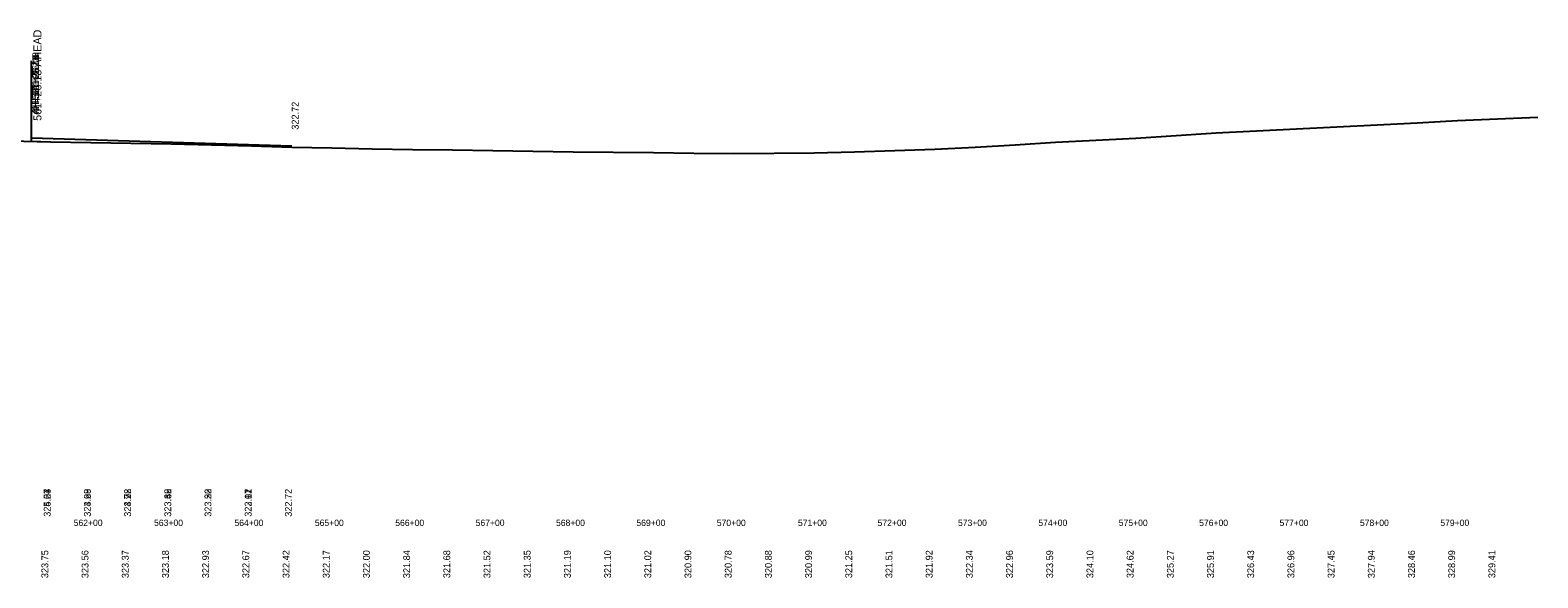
# Model space of a CAD drawing. Extents: x 1354 to 11940, y 17935 to 18885.
# Drawn here: x 10064 to 11940, y 17935 to 18616 of the extents above; entities that cross this region are included whole.
import ezdxf

# ---------------------------------------------------------------- set-up
doc = ezdxf.new("R2010")
doc.units = 0
for name, color, linetype in [('Level 1', 7, 'Continuous'), ('Level 40', 7, 'Continuous'), ('Level 41', 7, 'Continuous'), ('Level 42', 7, 'Continuous'), ('Level 43', 7, 'Continuous'), ('Level 45', 7, 'Continuous')]:
    doc.layers.add(name, color=color, linetype=linetype)

msp = doc.modelspace()

# ---------------------------------------------------------------- linework, layer by layer
at = {"layer": 'Level 1'}
msp.add_line((10065.9, 18477.7), (10065.9, 18577.7), dxfattribs=at)
at = {"layer": 'Level 40'}
for points in [[(10065.9, 18477.7), (10089.7, 18477.2), (10139.7, 18476.3), (10189.7, 18475.3), (10239.7, 18474.4), (10289.7, 18473.1), (10339.7, 18471.9), (10389.7, 18470.6), (10439.7, 18469.4), (10489.7, 18468.5), (10539.7, 18467.7), (10589.7, 18466.9), (10639.7, 18466.1), (10689.7, 18465.3), (10739.7, 18464.5), (10789.7, 18464), (10839.7, 18463.6), (10889.7, 18463), (10939.7, 18462.4), (10989.7, 18462.9), (11039.7, 18463.5), (11089.7, 18464.8), (11139.7, 18466.1), (11189.7, 18468.1), (11239.7, 18470.2), (11289.7, 18473.3), (11339.7, 18476.5), (11389.7, 18479), (11439.7, 18481.6), (11489.7, 18484.8), (11539.7, 18488.1), (11589.7, 18490.7), (11639.7, 18493.3), (11689.7, 18495.8), (11739.7, 18498.2), (11789.7, 18500.8), (11839.7, 18503.5), (11889.7, 18505.6), (11939.7, 18507.7)], [(10039.7, 18478.1), (10089.7, 18477.2), (10139.7, 18476.3), (10189.7, 18475.3), (10239.7, 18474.4), (10289.7, 18473.1), (10339.7, 18471.9), (10389.7, 18470.6)]]:
    msp.add_lwpolyline(points, dxfattribs=at)
at = {"layer": 'Level 45'}
msp.add_line((10065.9, 18481.9), (10389.7, 18472.1), dxfattribs=at)

# ---------------------------------------------------------------- texts
at = {"layer": 'Level 1'}
msp.add_text('561+26.18 AHEAD', height=10, rotation=90, dxfattribs=at).set_placement((10078.3, 18503.1))
at = {"layer": 'Level 41'}
for s, p in [('AH 561+26.18', (10075.4, 18515.4)), ('AH 561+26.18', (10075.4, 18512.5)), ('AH 561+26.18', (10075.4, 18510.9)), ('322.72', (10398.2, 18492.1))]:
    msp.add_text(s, height=8.5, rotation=90, dxfattribs=at).set_placement(p)
at = {"layer": 'Level 42'}
for s, p in [('562+00', (10118.4, 17999.5)), ('562+00', (10118.4, 17999.5)), ('563+00', (10218.4, 17999.5)), ('563+00', (10218.4, 17999.5)), ('564+00', (10318.4, 17999.5)), ('564+00', (10318.4, 17999.5)), ('565+00', (10418.4, 17999.5)), ('566+00', (10518.4, 17999.5)), ('567+00', (10618.4, 17999.5)), ('568+00', (10718.4, 17999.5)), ('569+00', (10818.4, 17999.5)), ('570+00', (10918.4, 17999.5)), ('571+00', (11019.3, 17999.5)), ('572+00', (11118.4, 17999.5)), ('573+00', (11218.4, 17999.5)), ('574+00', (11318.4, 17999.5)), ('575+00', (11418.4, 17999.5)), ('576+00', (11518.4, 17999.5)), ('577+00', (11618.4, 17999.5)), ('578+00', (11718.4, 17999.5)), ('579+00', (11818.4, 17999.5))]:
    msp.add_text(s, height=8, dxfattribs=at).set_placement(p)
at = {"layer": 'Level 43'}
for s, p in [('324.24', (10089.7, 18011)), ('324.53', (10089.7, 18011)), ('325.07', (10089.7, 18011)), ('324.68', (10139.7, 18011)), ('324.23', (10139.7, 18011)), ('323.99', (10139.7, 18011)), ('324.28', (10189.7, 18011)), ('323.73', (10189.7, 18011)), ('323.92', (10189.7, 18011)), ('323.48', (10239.7, 18011)), ('323.89', (10239.7, 18011)), ('323.62', (10239.7, 18011)), ('323.50', (10289.7, 18011)), ('323.23', (10289.7, 18011)), ('323.32', (10289.7, 18011)), ('323.11', (10339.7, 18011)), ('322.97', (10339.7, 18011)), ('323.02', (10339.7, 18011)), ('322.72', (10389.7, 18011)), ('322.72', (10389.7, 18011)), ('322.72', (10389.7, 18011)), ('323.75', (10086.8, 17934.7)), ('323.56', (10136.8, 17934.7)), ('323.37', (10186.8, 17934.7)), ('323.18', (10236.8, 17934.7)), ('322.93', (10286.8, 17934.7)), ('322.67', (10336.8, 17934.7)), ('322.42', (10386.8, 17934.7)), ('322.17', (10436.8, 17934.7)), ('322.00', (10486.8, 17934.7)), ('321.84', (10536.8, 17934.7)), ('321.68', (10586.8, 17934.7)), ('321.52', (10636.8, 17934.7)), ('321.35', (10686.8, 17934.7)), ('321.19', (10736.8, 17934.7)), ('321.10', (10786.8, 17934.7)), ('321.02', (10836.8, 17934.7)), ('320.90', (10886.8, 17934.7)), ('320.78', (10936.8, 17934.7)), ('320.88', (10986.8, 17934.7)), ('320.99', (11036.8, 17934.7)), ('321.25', (11086.8, 17934.7)), ('321.51', (11136.8, 17934.7)), ('321.92', (11186.8, 17934.7)), ('322.34', (11236.8, 17934.7)), ('322.96', (11286.8, 17934.7)), ('323.59', (11336.8, 17934.7)), ('324.10', (11386.8, 17934.7)), ('324.62', (11436.8, 17934.7)), ('325.27', (11486.8, 17934.7)), ('325.91', (11536.8, 17934.7)), ('326.43', (11586.8, 17934.7)), ('326.96', (11636.8, 17934.7)), ('327.45', (11686.8, 17934.7)), ('327.94', (11736.8, 17934.7)), ('328.46', (11786.8, 17934.7)), ('328.99', (11836.8, 17934.7)), ('329.41', (11886.8, 17934.7))]:
    msp.add_text(s, height=8.5, rotation=90, dxfattribs=at).set_placement(p)

doc.saveas('drawing.dxf')
